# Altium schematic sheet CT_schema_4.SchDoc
size 400 x 230 mm
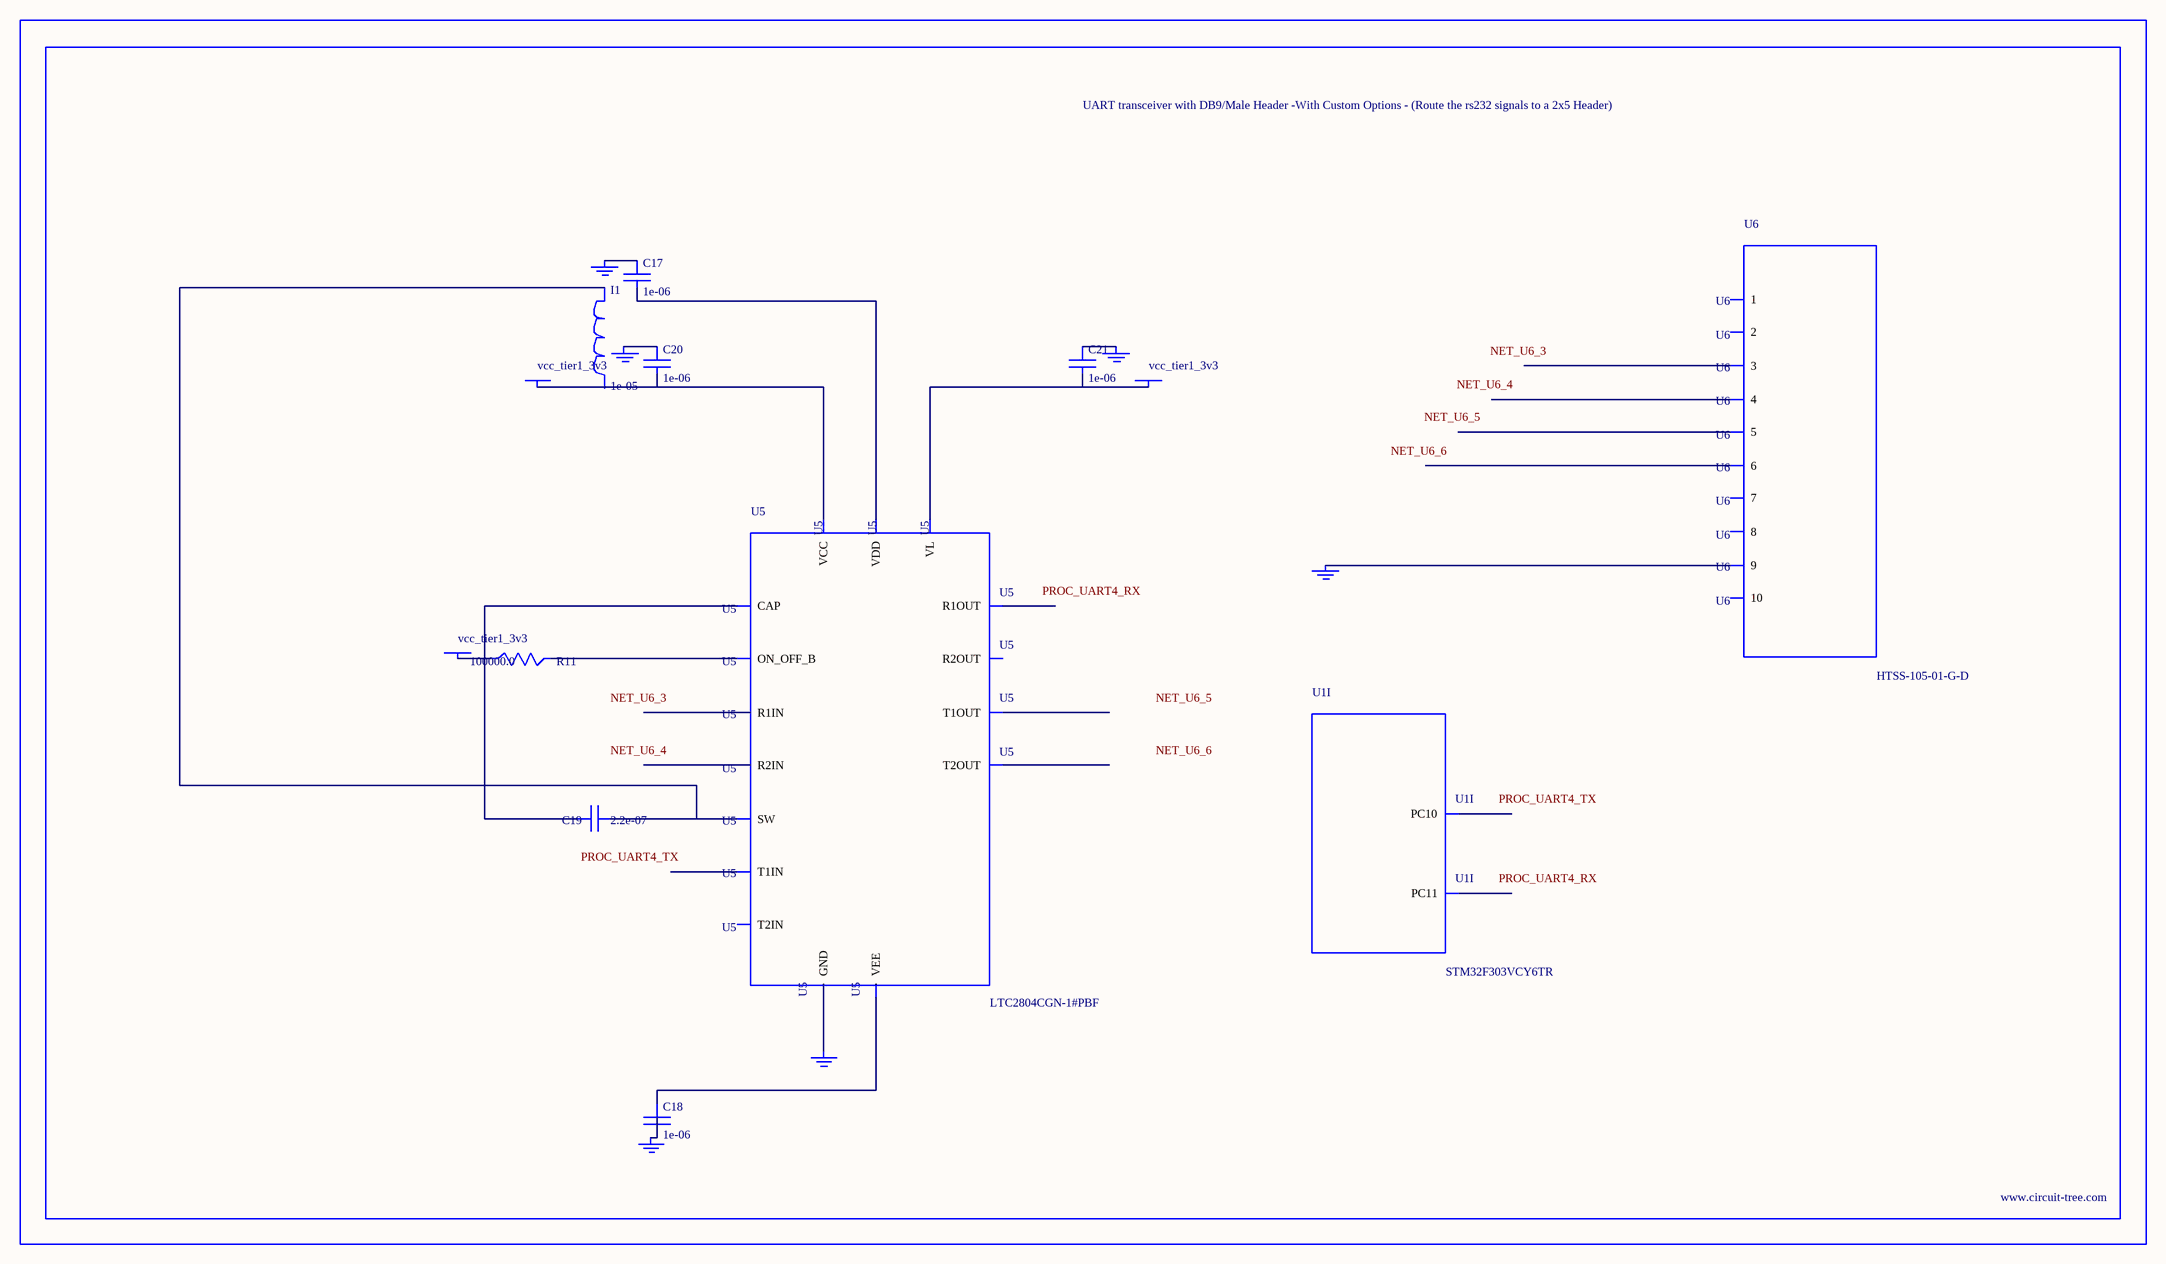
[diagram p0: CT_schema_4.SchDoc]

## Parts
BORDER3  (no value)
C17  1e-06  [C0603]
C18  1e-06  [C0603]
C19  2.2e-07  [C0603]
C20  1e-06  [C0603]
C21  1e-06  [C0603]
GND_INSTANCE_3_0  (no value)
GND_INSTANCE_3_1  (no value)
GND_INSTANCE_3_2  (no value)
GND_INSTANCE_3_3  (no value)
GND_INSTANCE_3_4  (no value)
GND_INSTANCE_3_5  (no value)
I1  1e-05  [L1210]
POWER_INSTANCE_3_0  vcc_tier1_3v3
POWER_INSTANCE_3_1  vcc_tier1_3v3
POWER_INSTANCE_3_2  vcc_tier1_3v3
R11  100000.0  [R0603]
U1  STM32F303VCY6TR  [WLCSP100]  (part I of 10)
U5  LTC2804CGN-1#PBF  [SSOP-16]
U6  HTSS-105-01-G-D  [HTSS-105-01-G-D]

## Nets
NetC17_1: C17.1 GND_INSTANCE_3_1.0(GND)
NetC17_2: C17.2 U5.6(VDD)
NetC18_1: C18.1 U5.9(VEE)
NetC18_2: C18.2 GND_INSTANCE_3_2.0(GND)
NetC19_1: C19.1 I1.1 U5.7(SW)
NetC19_2: C19.2 U5.10(CAP)
NetC20_1: C20.1 GND_INSTANCE_3_0.0(GND)
NetC20_2: C20.2 POWER_INSTANCE_3_0.0(PWR) U5.5(VCC)
NetC21_1: C21.1 GND_INSTANCE_3_3.0(GND)
NetC21_2: C21.2 POWER_INSTANCE_3_2.0(PWR) U5.12(VL)
NetGND_INSTANCE_3_4_0: GND_INSTANCE_3_4.0(GND) U5.8(GND)
NetGND_INSTANCE_3_5_0: GND_INSTANCE_3_5.0(GND) U6.9
NetPOWER_INSTANCE_3_1_0: POWER_INSTANCE_3_1.0(PWR) R11.1
NetR11_2: R11.2 U5.11(ON_OFF_B)

Not connected (* = marked no-connect by the designer): I1 2; U1 D3(PC11) E4(PC10); U5 1(R1IN) 2(R2IN) 3(T1OUT) 4(T2OUT) 13(T2IN) 14(T1IN) 15(R2OUT) 16(R1OUT); U6 1 2 3 4 5 6 7 8 10

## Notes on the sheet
- Labels drawn without touching a wire or pin: NET_U6_3, NET_U6_4, NET_U6_5, NET_U6_6, PROC_UART4_RX, PROC_UART4_TX

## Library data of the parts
BORDER3 = BORDER_PAGE3
C17 C18 C20 C21 = C0603C105K3RACTU
C19 = C0603C224K3RAC
GND_INSTANCE_3_0-GND_INSTANCE_3_5 = GND
I1 = CBC3225T100MR
POWER_INSTANCE_3_0-POWER_INSTANCE_3_2 = PWR
R11 = RC0603JR-07100KL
